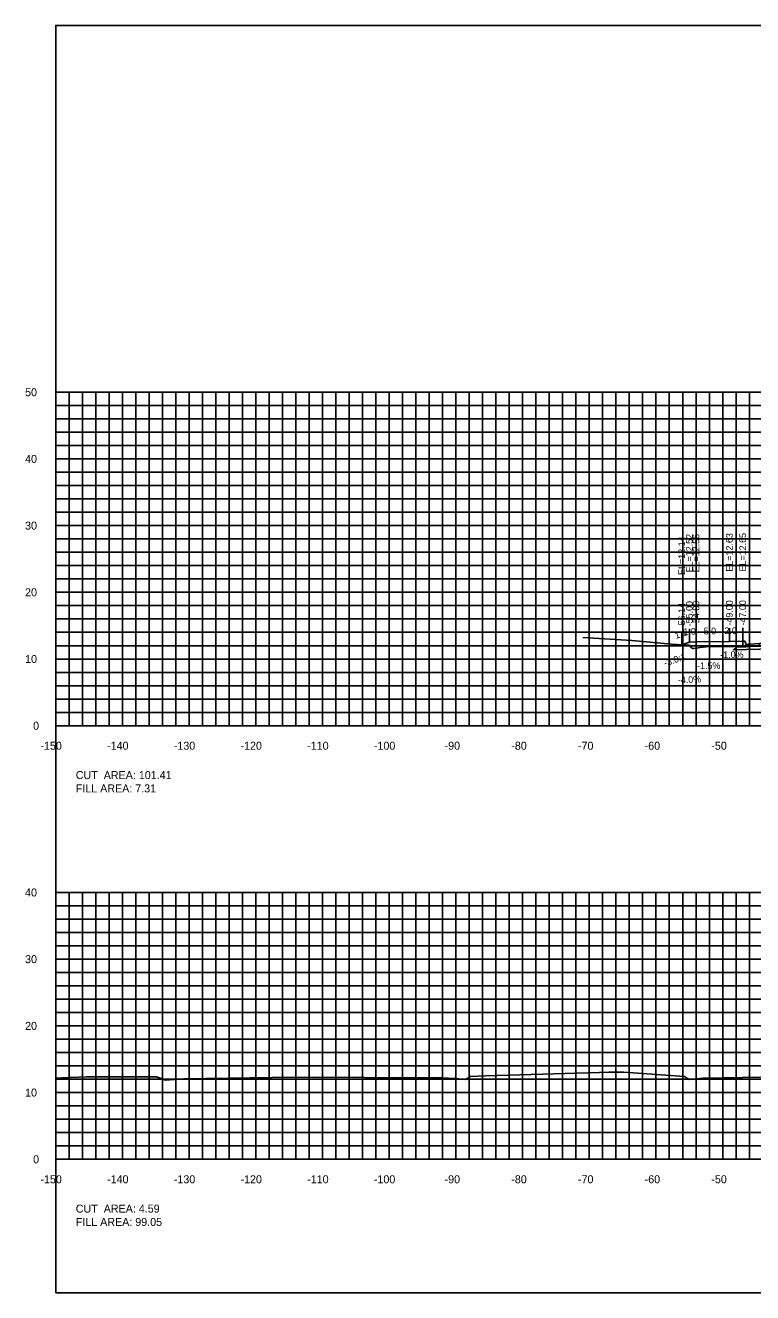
# Model space of a CAD drawing. Extents: x 1797682 to 1802785, y 249453 to 250269.
# Drawn here: x 1802136.4 to 1802245.5, y 250079.4 to 250269.4 of the extents above; entities that cross this region are included whole.
import ezdxf

# ---------------------------------------------------------------- set-up
doc = ezdxf.new("R2010")
doc.units = 0
for name, color, linetype in [('10', 7, 'Continuous'), ('3', 7, 'Continuous'), ('31', 7, 'Continuous'), ('4', 7, 'Continuous'), ('60', 7, 'Continuous'), ('ANNO-TXT', 7, 'Continuous'), ('BASE', 7, 'Continuous'), ('CL-CNST', 7, 'Continuous'), ('Level 62', 7, 'Continuous'), ('M-ROADS', 7, 'Continuous')]:
    doc.layers.add(name, color=color, linetype=linetype)

msp = doc.modelspace()

# ---------------------------------------------------------------- linework, layer by layer
for p, q in [((1802236, 250176.95), (1802236, 250178.95)), ((1802237, 250176.99), (1802237, 250178.99)), ((1802242, 250177.07), (1802242, 250179.07)), ((1802244, 250177.09), (1802244, 250179.09)), ((1802234.86, 250176.57), (1802234.86, 250178.57))]:
    msp.add_line(p, q)
for points in [[(1802141, 250079.43), (1802441, 250079.43), (1802441, 250269.43), (1802141, 250269.43)], [(1802246.5, 250176.75), (1802244.5, 250176.59), (1802244.33, 250177.09), (1802244, 250177.09), (1802244, 250176.25), (1802244.5, 250176.25), (1802246.5, 250176.41)]]:
    msp.add_lwpolyline(points, close=True)
at = {"layer": '60'}
for p, q in [((1802140.94, 250214.43), (1802141, 250214.43)), ((1802141, 250164.43), (1802141, 250214.43)), ((1802140.94, 250204.43), (1802141, 250204.43)), ((1802140.94, 250194.43), (1802141, 250194.43)), ((1802140.94, 250184.43), (1802141, 250184.43)), ((1802140.94, 250174.43), (1802141, 250174.43)), ((1802140.94, 250164.43), (1802141, 250164.43)), ((1802141, 250164.43), (1802441, 250164.43)), ((1802141, 250164.37), (1802141, 250164.43)), ((1802151, 250164.37), (1802151, 250164.43)), ((1802161, 250164.37), (1802161, 250164.43)), ((1802171, 250164.37), (1802171, 250164.43)), ((1802181, 250164.37), (1802181, 250164.43)), ((1802191, 250164.37), (1802191, 250164.43)), ((1802201, 250164.37), (1802201, 250164.43)), ((1802211, 250164.37), (1802211, 250164.43)), ((1802221, 250164.37), (1802221, 250164.43)), ((1802231, 250164.37), (1802231, 250164.43)), ((1802241, 250164.37), (1802241, 250164.43)), ((1802140.94, 250139.43), (1802141, 250139.43)), ((1802141, 250099.43), (1802141, 250139.43)), ((1802140.94, 250129.43), (1802141, 250129.43)), ((1802140.94, 250119.43), (1802141, 250119.43)), ((1802140.94, 250109.43), (1802141, 250109.43)), ((1802140.94, 250099.43), (1802141, 250099.43)), ((1802141, 250099.43), (1802441, 250099.43)), ((1802141, 250099.37), (1802141, 250099.43)), ((1802151, 250099.37), (1802151, 250099.43)), ((1802161, 250099.37), (1802161, 250099.43)), ((1802171, 250099.37), (1802171, 250099.43)), ((1802181, 250099.37), (1802181, 250099.43)), ((1802191, 250099.37), (1802191, 250099.43)), ((1802201, 250099.37), (1802201, 250099.43)), ((1802211, 250099.37), (1802211, 250099.43)), ((1802221, 250099.37), (1802221, 250099.43)), ((1802231, 250099.37), (1802231, 250099.43)), ((1802241, 250099.37), (1802241, 250099.43))]:
    msp.add_line(p, q, dxfattribs=at)
at = {"layer": 'BASE'}
msp.add_lwpolyline([(1802346.68, 250175.66), (1802350.58, 250175.57), (1802350.18, 250175.98), (1802349.18, 250176), (1802348.68, 250176), (1802346.68, 250176.16), (1802346.68, 250176.16), (1802291, 250177.39), (1802246.5, 250176.41), (1802246.5, 250176.41), (1802244.5, 250176.25), (1802244, 250176.25), (1802243, 250176.22), (1802242.6, 250175.82), (1802246.5, 250175.91), (1802291, 250176.89)], close=True, dxfattribs=at)
at = {"layer": 'CL-CNST'}
msp.add_lwpolyline([(1802234.86, 250176.57), (1802236, 250176.95), (1802237, 250176.99), (1802242, 250177.07), (1802244, 250177.09), (1802244.33, 250177.09), (1802244.5, 250176.59), (1802246.5, 250176.75), (1802291, 250177.73), (1802346.68, 250176.5), (1802348.68, 250176.34), (1802348.85, 250176.84), (1802349.18, 250176.84), (1802363.74, 250176.99)], dxfattribs=at)
at = {"layer": 'Level 62'}
for p, q in [((1802141, 250214.43), (1802441, 250214.43)), ((1802141, 250164.43), (1802141, 250214.43)), ((1802143, 250164.43), (1802143, 250214.43)), ((1802145, 250164.43), (1802145, 250214.43)), ((1802147, 250164.43), (1802147, 250214.43)), ((1802149, 250164.43), (1802149, 250214.43)), ((1802151, 250164.43), (1802151, 250214.43)), ((1802153, 250164.43), (1802153, 250214.43)), ((1802155, 250164.43), (1802155, 250214.43)), ((1802157, 250164.43), (1802157, 250214.43)), ((1802159, 250164.43), (1802159, 250214.43)), ((1802161, 250164.43), (1802161, 250214.43)), ((1802163, 250164.43), (1802163, 250214.43)), ((1802165, 250164.43), (1802165, 250214.43)), ((1802167, 250164.43), (1802167, 250214.43)), ((1802169, 250164.43), (1802169, 250214.43)), ((1802171, 250164.43), (1802171, 250214.43)), ((1802173, 250164.43), (1802173, 250214.43)), ((1802175, 250164.43), (1802175, 250214.43)), ((1802177, 250164.43), (1802177, 250214.43)), ((1802179, 250164.43), (1802179, 250214.43)), ((1802181, 250164.43), (1802181, 250214.43)), ((1802183, 250164.43), (1802183, 250214.43)), ((1802185, 250164.43), (1802185, 250214.43)), ((1802187, 250164.43), (1802187, 250214.43)), ((1802189, 250164.43), (1802189, 250214.43)), ((1802191, 250164.43), (1802191, 250214.43)), ((1802193, 250164.43), (1802193, 250214.43)), ((1802195, 250164.43), (1802195, 250214.43)), ((1802197, 250164.43), (1802197, 250214.43)), ((1802199, 250164.43), (1802199, 250214.43)), ((1802201, 250164.43), (1802201, 250214.43)), ((1802203, 250164.43), (1802203, 250214.43)), ((1802205, 250164.43), (1802205, 250214.43)), ((1802207, 250164.43), (1802207, 250214.43)), ((1802209, 250164.43), (1802209, 250214.43)), ((1802211, 250164.43), (1802211, 250214.43)), ((1802213, 250164.43), (1802213, 250214.43)), ((1802215, 250164.43), (1802215, 250214.43)), ((1802217, 250164.43), (1802217, 250214.43)), ((1802219, 250164.43), (1802219, 250214.43)), ((1802221, 250164.43), (1802221, 250214.43)), ((1802223, 250164.43), (1802223, 250214.43)), ((1802225, 250164.43), (1802225, 250214.43)), ((1802227, 250164.43), (1802227, 250214.43)), ((1802229, 250164.43), (1802229, 250214.43)), ((1802231, 250164.43), (1802231, 250214.43)), ((1802233, 250164.43), (1802233, 250214.43)), ((1802235, 250164.43), (1802235, 250214.43)), ((1802237, 250164.43), (1802237, 250214.43)), ((1802239, 250164.43), (1802239, 250214.43)), ((1802241, 250164.43), (1802241, 250214.43)), ((1802243, 250164.43), (1802243, 250214.43)), ((1802245, 250164.43), (1802245, 250214.43)), ((1802141, 250212.43), (1802441, 250212.43)), ((1802141, 250210.43), (1802441, 250210.43)), ((1802141, 250208.43), (1802441, 250208.43)), ((1802141, 250206.43), (1802441, 250206.43)), ((1802141, 250204.43), (1802441, 250204.43)), ((1802141, 250202.43), (1802441, 250202.43)), ((1802141, 250200.43), (1802441, 250200.43)), ((1802141, 250198.43), (1802441, 250198.43)), ((1802141, 250196.43), (1802441, 250196.43)), ((1802141, 250194.43), (1802441, 250194.43)), ((1802141, 250192.43), (1802441, 250192.43)), ((1802141, 250190.43), (1802441, 250190.43)), ((1802141, 250188.43), (1802441, 250188.43)), ((1802141, 250186.43), (1802441, 250186.43)), ((1802141, 250184.43), (1802441, 250184.43)), ((1802141, 250182.43), (1802441, 250182.43)), ((1802141, 250180.43), (1802441, 250180.43)), ((1802141, 250178.43), (1802441, 250178.43)), ((1802141, 250176.43), (1802441, 250176.43)), ((1802141, 250174.43), (1802441, 250174.43)), ((1802141, 250172.43), (1802441, 250172.43)), ((1802141, 250170.43), (1802441, 250170.43)), ((1802141, 250168.43), (1802441, 250168.43)), ((1802141, 250166.43), (1802441, 250166.43)), ((1802141, 250164.43), (1802441, 250164.43)), ((1802141, 250139.43), (1802441, 250139.43)), ((1802141, 250099.43), (1802141, 250139.43)), ((1802143, 250099.43), (1802143, 250139.43)), ((1802145, 250099.43), (1802145, 250139.43)), ((1802147, 250099.43), (1802147, 250139.43)), ((1802149, 250099.43), (1802149, 250139.43)), ((1802151, 250099.43), (1802151, 250139.43)), ((1802153, 250099.43), (1802153, 250139.43)), ((1802155, 250099.43), (1802155, 250139.43)), ((1802157, 250099.43), (1802157, 250139.43)), ((1802159, 250099.43), (1802159, 250139.43)), ((1802161, 250099.43), (1802161, 250139.43)), ((1802163, 250099.43), (1802163, 250139.43)), ((1802165, 250099.43), (1802165, 250139.43)), ((1802167, 250099.43), (1802167, 250139.43)), ((1802169, 250099.43), (1802169, 250139.43)), ((1802171, 250099.43), (1802171, 250139.43)), ((1802173, 250099.43), (1802173, 250139.43)), ((1802175, 250099.43), (1802175, 250139.43)), ((1802177, 250099.43), (1802177, 250139.43)), ((1802179, 250099.43), (1802179, 250139.43)), ((1802181, 250099.43), (1802181, 250139.43)), ((1802183, 250099.43), (1802183, 250139.43)), ((1802185, 250099.43), (1802185, 250139.43)), ((1802187, 250099.43), (1802187, 250139.43)), ((1802189, 250099.43), (1802189, 250139.43)), ((1802191, 250099.43), (1802191, 250139.43)), ((1802193, 250099.43), (1802193, 250139.43)), ((1802195, 250099.43), (1802195, 250139.43)), ((1802197, 250099.43), (1802197, 250139.43)), ((1802199, 250099.43), (1802199, 250139.43)), ((1802201, 250099.43), (1802201, 250139.43)), ((1802203, 250099.43), (1802203, 250139.43)), ((1802205, 250099.43), (1802205, 250139.43)), ((1802207, 250099.43), (1802207, 250139.43)), ((1802209, 250099.43), (1802209, 250139.43)), ((1802211, 250099.43), (1802211, 250139.43)), ((1802213, 250099.43), (1802213, 250139.43)), ((1802215, 250099.43), (1802215, 250139.43)), ((1802217, 250099.43), (1802217, 250139.43)), ((1802219, 250099.43), (1802219, 250139.43)), ((1802221, 250099.43), (1802221, 250139.43)), ((1802223, 250099.43), (1802223, 250139.43)), ((1802225, 250099.43), (1802225, 250139.43)), ((1802227, 250099.43), (1802227, 250139.43)), ((1802229, 250099.43), (1802229, 250139.43)), ((1802231, 250099.43), (1802231, 250139.43)), ((1802233, 250099.43), (1802233, 250139.43)), ((1802235, 250099.43), (1802235, 250139.43)), ((1802237, 250099.43), (1802237, 250139.43)), ((1802239, 250099.43), (1802239, 250139.43)), ((1802241, 250099.43), (1802241, 250139.43)), ((1802243, 250099.43), (1802243, 250139.43)), ((1802245, 250099.43), (1802245, 250139.43)), ((1802141, 250137.43), (1802441, 250137.43)), ((1802141, 250135.43), (1802441, 250135.43)), ((1802141, 250133.43), (1802441, 250133.43)), ((1802141, 250131.43), (1802441, 250131.43)), ((1802141, 250129.43), (1802441, 250129.43)), ((1802141, 250127.43), (1802441, 250127.43)), ((1802141, 250125.43), (1802441, 250125.43)), ((1802141, 250123.43), (1802441, 250123.43)), ((1802141, 250121.43), (1802441, 250121.43)), ((1802141, 250119.43), (1802441, 250119.43)), ((1802141, 250117.43), (1802441, 250117.43)), ((1802141, 250115.43), (1802441, 250115.43)), ((1802141, 250113.43), (1802441, 250113.43)), ((1802141, 250111.43), (1802441, 250111.43)), ((1802141, 250109.43), (1802441, 250109.43)), ((1802141, 250107.43), (1802441, 250107.43)), ((1802141, 250105.43), (1802441, 250105.43)), ((1802141, 250103.43), (1802441, 250103.43)), ((1802141, 250101.43), (1802441, 250101.43)), ((1802141, 250099.43), (1802441, 250099.43))]:
    msp.add_line(p, q, dxfattribs=at)
at = {"layer": 'M-ROADS'}
for points in [[(1802220.01, 250177.65), (1802227.4, 250177.19), (1802233.33, 250176.66), (1802235.84, 250176.52), (1802236.02, 250176.51), (1802236.24, 250176.23), (1802236.48, 250176.03), (1802236.66, 250176.01), (1802237.61, 250176.14), (1802238.5, 250176.24), (1802246.97, 250176.38)], [(1802141, 250111.59), (1802141.98, 250111.65), (1802145.63, 250111.78), (1802156.15, 250111.79), (1802156.35, 250111.71), (1802157.52, 250111.3), (1802158.11, 250111.34), (1802160.19, 250111.5), (1802173.43, 250111.67), (1802180.28, 250111.73), (1802187.3, 250111.69), (1802198.86, 250111.64), (1802200.95, 250111.53), (1802202.44, 250111.41), (1802202.94, 250111.68), (1802203.19, 250111.85), (1802205.48, 250111.95), (1802222.47, 250112.46), (1802223.94, 250112.47), (1802225.59, 250112.5), (1802226.2, 250112.47), (1802235.29, 250111.86), (1802235.73, 250111.55), (1802235.97, 250111.38), (1802236.63, 250111.45), (1802237.95, 250111.6), (1802243.95, 250111.7), (1802250.67, 250111.8)]]:
    msp.add_lwpolyline(points, dxfattribs=at)

# ---------------------------------------------------------------- texts
msp.add_text('-3.0:1', height=1, rotation=18.4349).set_placement((1802232.35, 250173.31))
at = {"layer": '10'}
for s, p in [('-150', (1802138.7, 250160.83)), ('-140', (1802148.7, 250160.83)), ('-130', (1802158.7, 250160.83)), ('-120', (1802168.7, 250160.83)), ('-110', (1802178.7, 250160.83)), ('-100', (1802188.7, 250160.83)), ('-90', (1802199.3, 250160.83)), ('-80', (1802209.3, 250160.83)), ('-70', (1802219.3, 250160.83)), ('-60', (1802229.3, 250160.83)), ('-50', (1802239.3, 250160.83)), ('-150', (1802138.7, 250095.83)), ('-140', (1802148.7, 250095.83)), ('-130', (1802158.7, 250095.83)), ('-120', (1802168.7, 250095.83)), ('-110', (1802178.7, 250095.83)), ('-100', (1802188.7, 250095.83)), ('-90', (1802199.3, 250095.83)), ('-80', (1802209.3, 250095.83)), ('-70', (1802219.3, 250095.83)), ('-60', (1802229.3, 250095.83)), ('-50', (1802239.3, 250095.83))]:
    msp.add_text(s, height=1.2, dxfattribs=at).set_placement(p)
at = {"layer": '3'}
for s, p in [('EL=12.14', (1802235.36, 250187.04)), ('EL=12.52', (1802236.5, 250187.42)), ('EL=12.56', (1802237.5, 250187.42)), ('EL=12.63', (1802242.5, 250187.54)), ('EL=12.65', (1802244.5, 250187.56)), ('-56.14', (1802235.36, 250179.03)), ('-55.00', (1802236.5, 250179.33)), ('-54.00', (1802237.5, 250179.37)), ('-49.00', (1802242.5, 250179.44)), ('-47.00', (1802244.5, 250179.46))]:
    msp.add_text(s, height=1, rotation=90, dxfattribs=at).set_placement(p)
at = {"layer": '31'}
for s, p in [('50', (1802136.4, 250213.83)), ('40', (1802136.4, 250203.83)), ('30', (1802136.4, 250193.83)), ('20', (1802136.4, 250183.83)), ('10', (1802136.4, 250173.83)), ('0', (1802137.6, 250163.83)), ('40', (1802136.4, 250138.83)), ('30', (1802136.4, 250128.83)), ('20', (1802136.4, 250118.83)), ('10', (1802136.4, 250108.83)), ('0', (1802137.6, 250098.83))]:
    msp.add_text(s, height=1.2, dxfattribs=at).set_placement(p)
at = {"layer": '4'}
for s, rotation, p in [('1.1', 18.4349, (1802233.99, 250177.44)), ('1.0', 2.2906, (1802235.14, 250178.02)), ('5.0', 0.8594, (1802238.16, 250178.11)), ('2.0', 0.5729, (1802241.26, 250178.16)), ('-1.0%', 0.5729, (1802240.64, 250174.57)), ('-1.5%', 0.8594, (1802237.17, 250172.9)), ('-4.0%', 2.2906, (1802234.29, 250170.78))]:
    msp.add_text(s, height=1, rotation=rotation, dxfattribs=at).set_placement(p)
at = {"layer": '60'}
for p in [(1802141, 250164.43), (1802141, 250099.43)]:
    msp.add_text('-', height=0.0001, dxfattribs=at).set_placement(p)
at = {"layer": 'ANNO-TXT'}
for s, p in [('CUT  AREA: 101.41', (1802144, 250156.43)), ('FILL AREA: 7.31', (1802144, 250154.43)), ('CUT  AREA: 4.59', (1802144, 250091.43)), ('FILL AREA: 99.05', (1802144, 250089.43))]:
    msp.add_text(s, height=1.2, dxfattribs=at).set_placement(p)

doc.saveas('drawing.dxf')
